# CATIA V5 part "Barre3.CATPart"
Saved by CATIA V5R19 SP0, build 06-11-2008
Part number: Barre3
Bounding box of the stored display mesh (mm): x 2.449 to 22.751, y -4.064 to 21.664, z 13.526 to 16.474
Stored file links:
  F:\IAO\Catia\Barre3.CATPart
  F:\IAO\Catia\Etau.CATProduct
  F:\IAO\Catia\Squelette_Barre3.CATPart
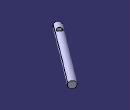
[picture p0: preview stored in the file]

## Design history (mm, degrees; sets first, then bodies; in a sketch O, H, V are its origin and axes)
Set1
  Plane1: linked copy from another document
  Line1: linked copy from another document
  Point1: linked copy from another document
Body1 (main body)
  Sketch1 on Plane1, origin (0, 0, 15), H (1, 0, 0), V (0, 1, 0)
    line L1 (21.6, 20.8) -> (22.8, 19.9)
    line L2 (22.8, 19.9) -> (4.8, -4.1)
    line L3 (4.8, -4.1) -> (3.6, -3.2)
    line L4 (3.6, -3.2) -> (21.6, 20.8)
    reference projected line E1 (15, 12) -> (6, 0) from Line1
    reference projected point E2 (6, 0) from Point1
    length L1 = 1.5
    length L2 = 30
    distance L3 E2 = 4
    coincidence: L4 E1
    perpendicularity: L1 L4, L3 L2
  Shaft1: profile Sketch1, axis Line1, angle 360
  Sketch2 on Plane1, origin (0, 0, 15), H (1, 0, 0), V (0, 1, 0)
    circle A1 centre (6, 0) radius 1
    point P1 (6, 0)
    reference projected point E1 (6, 0) from Point1
    radius A1 = 1
    coincidence: P1 E1
  Pocket1: profile Sketch2, direction (0, 0, -1), length 5, mirrored extent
